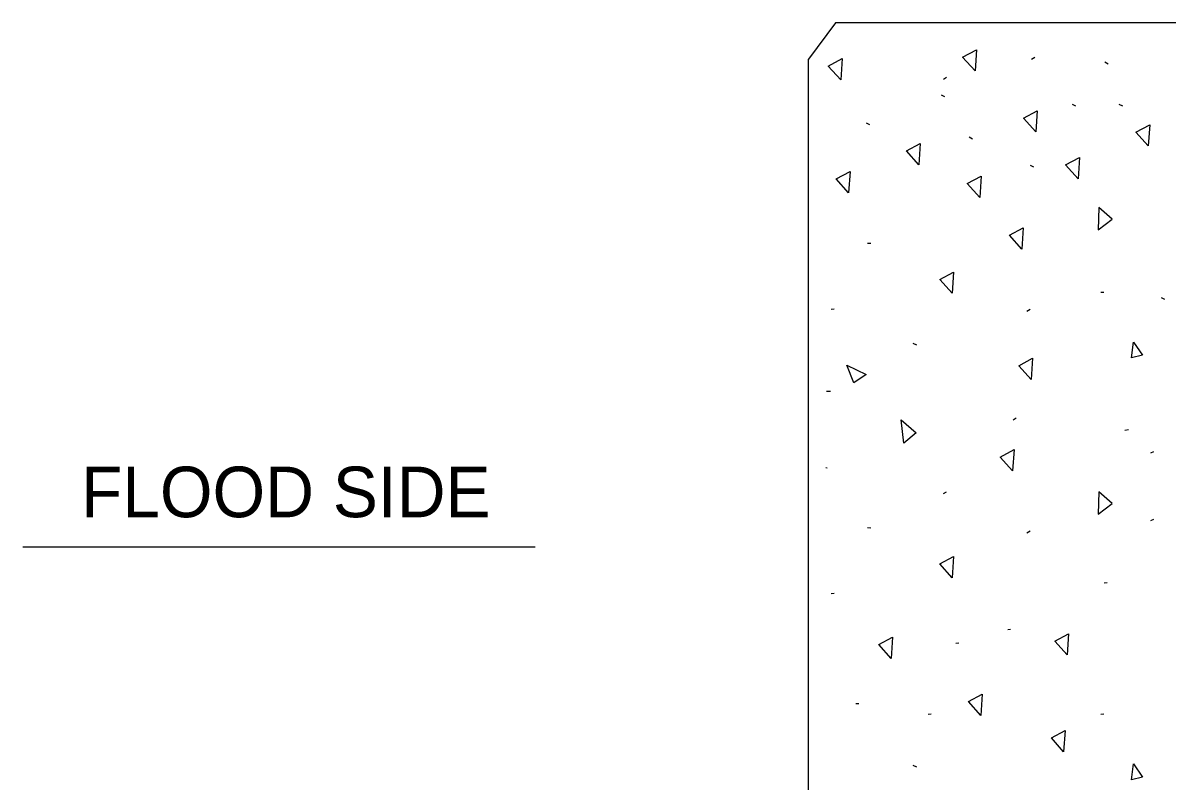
# Model space of a CAD drawing. Extents: x 22388.1 to 22405.7, y 22369.6 to 22390.4.
# Drawn here: x 22393.628 to 22394.947, y 22389.132 to 22390.006 of the extents above; entities that cross this region are included whole.
import ezdxf

# ---------------------------------------------------------------- set-up
doc = ezdxf.new("R2010")
doc.units = 0
for name, color, linetype in [('Level 10', 7, 'Continuous'), ('Level 3', 7, 'Continuous'), ('Level 44', 7, 'Continuous'), ('Level 7', 7, 'Continuous')]:
    doc.layers.add(name, color=color, linetype=linetype)

msp = doc.modelspace()

# ---------------------------------------------------------------- linework, layer by layer
at = {"layer": 'Level 10'}
msp.add_line((22394.2181, 22389.4013), (22393.6275, 22389.4013), dxfattribs=at)
at = {"layer": 'Level 3'}
msp.add_line((22394.5335, 22389.3491), (22394.5335, 22389.3559), dxfattribs=at)
at = {"layer": 'Level 44'}
for p, q in [((22394.7907, 22389.9641), (22394.7945, 22389.9664)), ((22394.8751, 22389.9609), (22394.8791, 22389.9589)), ((22394.6889, 22389.9411), (22394.6926, 22389.9434)), ((22394.6862, 22389.9231), (22394.6902, 22389.9211)), ((22394.8373, 22389.9123), (22394.8413, 22389.9103)), ((22394.8913, 22389.9123), (22394.8953, 22389.9103)), ((22394.5998, 22389.8907), (22394.6038, 22389.8887)), ((22394.7186, 22389.8744), (22394.7226, 22389.8724)), ((22394.7888, 22389.842), (22394.7928, 22389.84)), ((22394.6015, 22389.7521), (22394.6052, 22389.7518)), ((22394.8705, 22389.6954), (22394.8739, 22389.6956)), ((22394.5595, 22389.6759), (22394.5628, 22389.6764)), ((22394.9399, 22389.6893), (22394.9439, 22389.6873)), ((22394.7853, 22389.6737), (22394.789, 22389.6759)), ((22394.6538, 22389.6366), (22394.6578, 22389.6346)), ((22394.5541, 22389.5813), (22394.5586, 22389.5813)), ((22394.7692, 22389.5484), (22394.773, 22389.5507)), ((22394.898, 22389.5363), (22394.9023, 22389.537)), ((22394.9281, 22389.5101), (22394.9317, 22389.5118)), ((22394.5535, 22389.4932), (22394.555, 22389.4928)), ((22394.6889, 22389.4632), (22394.6926, 22389.4654)), ((22394.9281, 22389.4322), (22394.9317, 22389.4339)), ((22394.6015, 22389.4242), (22394.6052, 22389.4239)), ((22394.7853, 22389.4181), (22394.789, 22389.4204)), ((22394.8745, 22389.3605), (22394.8778, 22389.3607)), ((22394.5595, 22389.3479), (22394.5628, 22389.3485)), ((22394.7631, 22389.3067), (22394.7664, 22389.3069)), ((22394.7034, 22389.2908), (22394.7067, 22389.291)), ((22394.5879, 22389.2211), (22394.5913, 22389.2213)), ((22394.6715, 22389.2091), (22394.6749, 22389.2094)), ((22394.8705, 22389.2091), (22394.8739, 22389.2094)), ((22394.6538, 22389.1503), (22394.6578, 22389.1483))]:
    msp.add_line(p, q, dxfattribs=at)
for points in [[(22394.7254, 22389.9505), (22394.7111, 22389.9665), (22394.7271, 22389.975)], [(22394.5705, 22389.9402), (22394.5562, 22389.9562), (22394.5721, 22389.9647)], [(22394.7956, 22389.8802), (22394.7813, 22389.8962), (22394.7972, 22389.9047)], [(22394.9251, 22389.864), (22394.9109, 22389.88), (22394.9268, 22389.8885)], [(22394.6606, 22389.8424), (22394.6463, 22389.8584), (22394.6623, 22389.8669)], [(22394.8442, 22389.8262), (22394.8299, 22389.8422), (22394.8458, 22389.8507)], [(22394.5796, 22389.81), (22394.5654, 22389.826), (22394.5813, 22389.8345)], [(22394.7308, 22389.8046), (22394.7165, 22389.8206), (22394.7325, 22389.8291)], [(22394.8674, 22389.7675), (22394.8834, 22389.7796), (22394.868, 22389.7932)], [(22394.7794, 22389.7451), (22394.7651, 22389.7611), (22394.781, 22389.7696)], [(22394.699, 22389.6942), (22394.6848, 22389.7102), (22394.7007, 22389.7187)], [(22394.9058, 22389.6197), (22394.9081, 22389.6379), (22394.9184, 22389.6227)], [(22394.5856, 22389.591), (22394.5777, 22389.6114), (22394.5998, 22389.6007)], [(22394.7901, 22389.5947), (22394.7759, 22389.6107), (22394.7918, 22389.6192)], [(22394.6403, 22389.5483), (22394.6574, 22389.5334), (22394.6432, 22389.5214)], [(22394.7687, 22389.4894), (22394.7545, 22389.5054), (22394.7704, 22389.5139)], [(22394.8674, 22389.4396), (22394.8834, 22389.4517), (22394.868, 22389.4653)], [(22394.699, 22389.3663), (22394.6848, 22389.3823), (22394.7007, 22389.3908)], [(22394.6286, 22389.2732), (22394.6144, 22389.2892), (22394.6303, 22389.2977)], [(22394.8316, 22389.2772), (22394.8173, 22389.2932), (22394.8333, 22389.3017)], [(22394.7321, 22389.2075), (22394.7178, 22389.2235), (22394.7338, 22389.232)], [(22394.8276, 22389.1657), (22394.8134, 22389.1817), (22394.8293, 22389.1902)], [(22394.9058, 22389.1334), (22394.9081, 22389.1517), (22394.9184, 22389.1364)]]:
    msp.add_lwpolyline(points, close=True, dxfattribs=at)
at = {"layer": 'Level 7'}
for p, q in [((22394.5647, 22390.0059), (22394.5335, 22389.9643)), ((22395.0022, 22390.0059), (22394.5647, 22390.0059)), ((22394.5335, 22388.5559), (22394.5335, 22389.9643))]:
    msp.add_line(p, q, dxfattribs=at)

# ---------------------------------------------------------------- texts
at = {"layer": 'Level 10'}
msp.add_text('FLOOD SIDE', height=0.05833, dxfattribs=at).set_placement((22393.6945, 22389.436))

doc.saveas('drawing.dxf')
